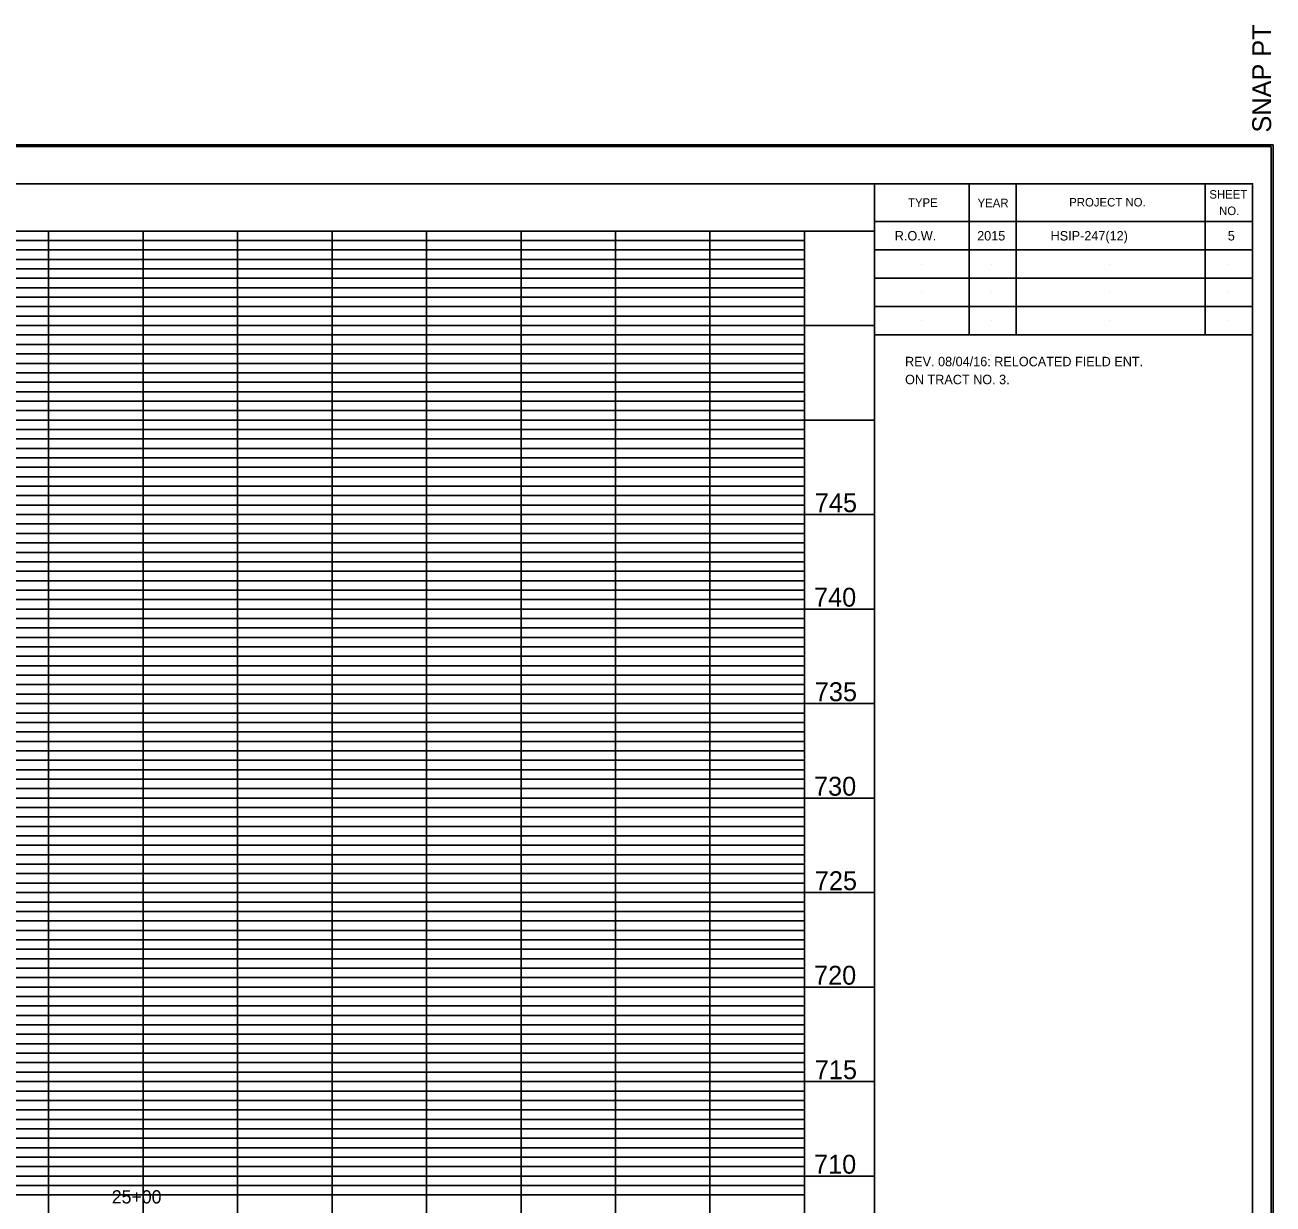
# Model space of a CAD drawing. Extents: x -200 to 1681865, y -325 to 520634.
# Drawn here: x 1681205 to 1681865, y 520010 to 520634 of the extents above; entities that cross this region are included whole.
import ezdxf

# ---------------------------------------------------------------- set-up
doc = ezdxf.new("R2010")
doc.units = 0
for name, color, linetype in [('DESIGN - SCRATCH - User 1', 7, 'Continuous'), ('DESIGN - SHEET - Corner Text', 7, 'Continuous'), ('DESIGN - SHEET - Light Grid', 7, 'Continuous'), ('DESIGN - SHEET - Linework', 7, 'Continuous'), ('DESIGN - SHEET - Plot Shape', 7, 'Continuous')]:
    doc.layers.add(name, color=color, linetype=linetype)

msp = doc.modelspace()

# ---------------------------------------------------------------- linework, layer by layer
at = {"layer": 'DESIGN - SCRATCH - User 1'}
for p, q in [((1681679.23, 520522.26), (1681679.23, 520522.26)), ((1681716.23, 520522.26), (1681716.23, 520522.26)), ((1681778.73, 520522.26), (1681778.73, 520522.26)), ((1681841.23, 520522.26), (1681841.23, 520522.26)), ((1681679.23, 520507.26), (1681679.23, 520507.26)), ((1681716.23, 520507.26), (1681716.23, 520507.26)), ((1681778.73, 520507.26), (1681778.73, 520507.26)), ((1681841.23, 520507.26), (1681841.23, 520507.26)), ((1681679.23, 520492.26), (1681679.23, 520492.26)), ((1681716.23, 520492.26), (1681716.23, 520492.26)), ((1681778.73, 520492.26), (1681778.73, 520492.26)), ((1681841.23, 520492.26), (1681841.23, 520492.26)), ((1681679.23, 520477.26), (1681679.23, 520477.26)), ((1681716.23, 520477.26), (1681716.23, 520477.26)), ((1681778.73, 520477.26), (1681778.73, 520477.26)), ((1681841.23, 520477.26), (1681841.23, 520477.26))]:
    msp.add_line(p, q, dxfattribs=at)
at = {"layer": 'DESIGN - SHEET - Light Grid'}
for p, q in [((1680967.13, 520519.76), (1681317.13, 520519.76)), ((1680967.13, 520514.76), (1681317.13, 520514.76)), ((1681317.13, 520519.76), (1681617.13, 520519.76)), ((1681317.13, 520514.76), (1681617.13, 520514.76)), ((1680967.13, 520509.76), (1681317.13, 520509.76)), ((1681317.13, 520509.76), (1681617.13, 520509.76)), ((1680967.13, 520504.76), (1681317.13, 520504.76)), ((1681317.13, 520504.76), (1681617.13, 520504.76)), ((1680967.13, 520499.76), (1681317.13, 520499.76)), ((1680967.13, 520494.76), (1681317.13, 520494.76)), ((1681317.13, 520499.76), (1681617.13, 520499.76)), ((1681317.13, 520494.76), (1681617.13, 520494.76)), ((1680967.13, 520489.76), (1681317.13, 520489.76)), ((1681317.13, 520489.76), (1681617.13, 520489.76)), ((1680967.13, 520484.76), (1681317.13, 520484.76)), ((1681317.13, 520484.76), (1681617.13, 520484.76)), ((1680967.13, 520479.76), (1681317.13, 520479.76)), ((1681317.13, 520479.76), (1681617.13, 520479.76)), ((1680967.13, 520469.76), (1681317.13, 520469.76)), ((1681317.13, 520469.76), (1681617.13, 520469.76)), ((1680967.13, 520464.76), (1681317.13, 520464.76)), ((1681317.13, 520464.76), (1681617.13, 520464.76)), ((1680967.13, 520459.76), (1681317.13, 520459.76)), ((1680967.13, 520454.76), (1681317.13, 520454.76)), ((1681317.13, 520459.76), (1681617.13, 520459.76)), ((1681317.13, 520454.76), (1681617.13, 520454.76)), ((1680967.13, 520449.76), (1681317.13, 520449.76)), ((1681317.13, 520449.76), (1681617.13, 520449.76)), ((1680967.13, 520444.76), (1681317.13, 520444.76)), ((1681317.13, 520444.76), (1681617.13, 520444.76)), ((1680967.13, 520439.76), (1681317.13, 520439.76)), ((1680967.13, 520434.76), (1681317.13, 520434.76)), ((1681317.13, 520439.76), (1681617.13, 520439.76)), ((1681317.13, 520434.76), (1681617.13, 520434.76)), ((1680967.13, 520429.76), (1681317.13, 520429.76)), ((1681317.13, 520429.76), (1681617.13, 520429.76)), ((1680967.13, 520419.76), (1681317.13, 520419.76)), ((1681317.13, 520419.76), (1681617.13, 520419.76)), ((1680967.13, 520414.76), (1681317.13, 520414.76)), ((1680967.13, 520409.76), (1681317.13, 520409.76)), ((1681317.13, 520414.76), (1681617.13, 520414.76)), ((1681317.13, 520409.76), (1681617.13, 520409.76)), ((1680967.13, 520404.76), (1681317.13, 520404.76)), ((1681317.13, 520404.76), (1681617.13, 520404.76)), ((1680967.13, 520399.76), (1681317.13, 520399.76)), ((1681317.13, 520399.76), (1681617.13, 520399.76)), ((1680967.13, 520394.76), (1681317.13, 520394.76)), ((1680967.13, 520389.76), (1681317.13, 520389.76)), ((1681317.13, 520394.76), (1681617.13, 520394.76)), ((1681317.13, 520389.76), (1681617.13, 520389.76)), ((1680967.13, 520384.76), (1681317.13, 520384.76)), ((1681317.13, 520384.76), (1681617.13, 520384.76)), ((1680967.13, 520379.76), (1681317.13, 520379.76)), ((1681317.13, 520379.76), (1681617.13, 520379.76)), ((1680967.13, 520369.76), (1681317.13, 520369.76)), ((1681317.13, 520369.76), (1681617.13, 520369.76)), ((1680967.13, 520364.76), (1681317.13, 520364.76)), ((1681317.13, 520364.76), (1681617.13, 520364.76)), ((1680967.13, 520359.76), (1681317.13, 520359.76)), ((1681317.13, 520359.76), (1681617.13, 520359.76)), ((1680967.13, 520354.76), (1681317.13, 520354.76)), ((1680967.13, 520349.76), (1681317.13, 520349.76)), ((1681317.13, 520354.76), (1681617.13, 520354.76)), ((1681317.13, 520349.76), (1681617.13, 520349.76)), ((1680967.13, 520344.76), (1681317.13, 520344.76)), ((1681317.13, 520344.76), (1681617.13, 520344.76)), ((1680967.13, 520339.76), (1681317.13, 520339.76)), ((1681317.13, 520339.76), (1681617.13, 520339.76)), ((1680967.13, 520334.76), (1681317.13, 520334.76)), ((1680967.13, 520329.76), (1681317.13, 520329.76)), ((1681317.13, 520334.76), (1681617.13, 520334.76)), ((1681317.13, 520329.76), (1681617.13, 520329.76)), ((1680967.13, 520319.76), (1681317.13, 520319.76)), ((1681317.13, 520319.76), (1681617.13, 520319.76)), ((1680967.13, 520314.76), (1681317.13, 520314.76)), ((1680967.13, 520309.76), (1681317.13, 520309.76)), ((1681317.13, 520314.76), (1681617.13, 520314.76)), ((1681317.13, 520309.76), (1681617.13, 520309.76)), ((1680967.13, 520304.76), (1681317.13, 520304.76)), ((1681317.13, 520304.76), (1681617.13, 520304.76)), ((1680967.13, 520299.76), (1681317.13, 520299.76)), ((1681317.13, 520299.76), (1681617.13, 520299.76)), ((1680967.13, 520294.76), (1681317.13, 520294.76)), ((1680967.13, 520289.76), (1681317.13, 520289.76)), ((1681317.13, 520294.76), (1681617.13, 520294.76)), ((1681317.13, 520289.76), (1681617.13, 520289.76)), ((1680967.13, 520284.76), (1681317.13, 520284.76)), ((1681317.13, 520284.76), (1681617.13, 520284.76)), ((1680967.13, 520279.76), (1681317.13, 520279.76)), ((1681317.13, 520279.76), (1681617.13, 520279.76)), ((1680967.13, 520269.76), (1681317.13, 520269.76)), ((1681317.13, 520269.76), (1681617.13, 520269.76)), ((1680967.13, 520264.76), (1681317.13, 520264.76)), ((1681317.13, 520264.76), (1681617.13, 520264.76)), ((1680967.13, 520259.76), (1681317.13, 520259.76)), ((1681317.13, 520259.76), (1681617.13, 520259.76)), ((1680967.13, 520254.76), (1681317.13, 520254.76)), ((1680967.13, 520249.76), (1681317.13, 520249.76)), ((1681317.13, 520254.76), (1681617.13, 520254.76)), ((1681317.13, 520249.76), (1681617.13, 520249.76)), ((1680967.13, 520244.76), (1681317.13, 520244.76)), ((1681317.13, 520244.76), (1681617.13, 520244.76)), ((1680967.13, 520239.76), (1681317.13, 520239.76)), ((1681317.13, 520239.76), (1681617.13, 520239.76)), ((1680967.13, 520234.76), (1681317.13, 520234.76)), ((1681317.13, 520234.76), (1681617.13, 520234.76)), ((1680967.13, 520229.76), (1681317.13, 520229.76)), ((1681317.13, 520229.76), (1681617.13, 520229.76)), ((1680967.13, 520219.76), (1681317.13, 520219.76)), ((1681317.13, 520219.76), (1681617.13, 520219.76)), ((1680967.13, 520214.76), (1681317.13, 520214.76)), ((1681317.13, 520214.76), (1681617.13, 520214.76)), ((1680967.13, 520209.76), (1681317.13, 520209.76)), ((1680967.13, 520204.76), (1681317.13, 520204.76)), ((1681317.13, 520209.76), (1681617.13, 520209.76)), ((1681317.13, 520204.76), (1681617.13, 520204.76)), ((1680967.13, 520199.76), (1681317.13, 520199.76)), ((1681317.13, 520199.76), (1681617.13, 520199.76)), ((1680967.13, 520194.76), (1681317.13, 520194.76)), ((1681317.13, 520194.76), (1681617.13, 520194.76)), ((1680967.13, 520189.76), (1681317.13, 520189.76)), ((1680967.13, 520184.76), (1681317.13, 520184.76)), ((1681317.13, 520189.76), (1681617.13, 520189.76)), ((1681317.13, 520184.76), (1681617.13, 520184.76)), ((1680967.13, 520179.76), (1681317.13, 520179.76)), ((1681317.13, 520179.76), (1681617.13, 520179.76)), ((1680967.13, 520169.76), (1681317.13, 520169.76)), ((1680967.13, 520164.76), (1681317.13, 520164.76)), ((1681317.13, 520169.76), (1681617.13, 520169.76)), ((1681317.13, 520164.76), (1681617.13, 520164.76)), ((1680967.13, 520159.76), (1681317.13, 520159.76)), ((1681317.13, 520159.76), (1681617.13, 520159.76)), ((1680967.13, 520154.76), (1681317.13, 520154.76)), ((1681317.13, 520154.76), (1681617.13, 520154.76)), ((1680967.13, 520149.76), (1681317.13, 520149.76)), ((1680967.13, 520144.76), (1681317.13, 520144.76)), ((1681317.13, 520149.76), (1681617.13, 520149.76)), ((1681317.13, 520144.76), (1681617.13, 520144.76)), ((1680967.13, 520139.76), (1681317.13, 520139.76)), ((1681317.13, 520139.76), (1681617.13, 520139.76)), ((1680967.13, 520134.76), (1681317.13, 520134.76)), ((1681317.13, 520134.76), (1681617.13, 520134.76)), ((1680967.13, 520129.76), (1681317.13, 520129.76)), ((1681317.13, 520129.76), (1681617.13, 520129.76)), ((1680967.13, 520119.76), (1681317.13, 520119.76)), ((1681317.13, 520119.76), (1681617.13, 520119.76)), ((1680967.13, 520114.76), (1681317.13, 520114.76)), ((1681317.13, 520114.76), (1681617.13, 520114.76)), ((1680967.13, 520109.76), (1681317.13, 520109.76)), ((1680967.13, 520104.76), (1681317.13, 520104.76)), ((1681317.13, 520109.76), (1681617.13, 520109.76)), ((1681317.13, 520104.76), (1681617.13, 520104.76)), ((1680967.13, 520099.76), (1681317.13, 520099.76)), ((1681317.13, 520099.76), (1681617.13, 520099.76)), ((1680967.13, 520094.76), (1681317.13, 520094.76)), ((1681317.13, 520094.76), (1681617.13, 520094.76)), ((1680967.13, 520089.76), (1681317.13, 520089.76)), ((1680967.13, 520084.76), (1681317.13, 520084.76)), ((1681317.13, 520089.76), (1681617.13, 520089.76)), ((1681317.13, 520084.76), (1681617.13, 520084.76)), ((1680967.13, 520079.76), (1681317.13, 520079.76)), ((1681317.13, 520079.76), (1681617.13, 520079.76)), ((1680967.13, 520069.76), (1681317.13, 520069.76)), ((1680967.13, 520064.76), (1681317.13, 520064.76)), ((1681317.13, 520069.76), (1681617.13, 520069.76)), ((1681317.13, 520064.76), (1681617.13, 520064.76)), ((1680967.13, 520059.76), (1681317.13, 520059.76)), ((1681317.13, 520059.76), (1681617.13, 520059.76)), ((1680967.13, 520054.76), (1681317.13, 520054.76)), ((1681317.13, 520054.76), (1681617.13, 520054.76)), ((1680967.13, 520049.76), (1681317.13, 520049.76)), ((1681317.13, 520049.76), (1681617.13, 520049.76)), ((1680967.13, 520044.76), (1681317.13, 520044.76)), ((1680967.13, 520039.76), (1681317.13, 520039.76)), ((1681317.13, 520044.76), (1681617.13, 520044.76)), ((1681317.13, 520039.76), (1681617.13, 520039.76)), ((1680967.13, 520034.76), (1681317.13, 520034.76)), ((1681317.13, 520034.76), (1681617.13, 520034.76)), ((1680967.13, 520029.76), (1681317.13, 520029.76)), ((1681317.13, 520029.76), (1681617.13, 520029.76)), ((1680967.13, 520019.76), (1681317.13, 520019.76)), ((1681317.13, 520019.76), (1681617.13, 520019.76)), ((1680967.13, 520014.76), (1681317.13, 520014.76)), ((1681317.13, 520014.76), (1681617.13, 520014.76))]:
    msp.add_line(p, q, dxfattribs=at)
at = {"layer": 'DESIGN - SHEET - Linework'}
for p, q in [((1680163.08, 520570.46), (1681865.08, 520570.46)), ((1681865.08, 520570.46), (1681865.08, 519479.06)), ((1680282.13, 520524.76), (1681654.23, 520524.76)), ((1681217.13, 519524.76), (1681217.13, 520524.76)), ((1681267.13, 519524.76), (1681267.13, 520524.76)), ((1681317.13, 519524.76), (1681317.13, 520524.76)), ((1681367.13, 519524.76), (1681367.13, 520524.76)), ((1681417.13, 519524.76), (1681417.13, 520524.76)), ((1681467.13, 519524.76), (1681467.13, 520524.76)), ((1681517.13, 519524.76), (1681517.13, 520524.76)), ((1681567.13, 519524.76), (1681567.13, 520524.76)), ((1681617.13, 519524.76), (1681617.13, 520524.76)), ((1680280.03, 520474.76), (1681654.23, 520474.76)), ((1680280.03, 520424.76), (1681654.23, 520424.76)), ((1680280.03, 520374.76), (1681654.23, 520374.76)), ((1680280.03, 520324.76), (1681654.23, 520324.76)), ((1680280.03, 520274.76), (1681654.23, 520274.76)), ((1680280.03, 520224.76), (1681654.23, 520224.76)), ((1680280.03, 520174.76), (1681654.23, 520174.76)), ((1680280.03, 520124.76), (1681654.23, 520124.76)), ((1680280.03, 520074.76), (1681654.23, 520074.76)), ((1680280.03, 520024.76), (1681654.23, 520024.76))]:
    msp.add_line(p, q, dxfattribs=at)
for points in [[(1680280.03, 520549.76), (1680280.03, 519499.76), (1681854.23, 519499.76), (1681854.23, 520549.76), (1680280.03, 520549.76)], [(1681654.23, 520549.76), (1681654.23, 520469.76), (1681854.23, 520469.76), (1681854.23, 520549.76), (1681829.23, 520549.76), (1681829.23, 520469.76), (1681729.23, 520469.76), (1681729.23, 520549.76), (1681704.23, 520549.76), (1681704.23, 520469.76), (1681654.23, 520469.76), (1681654.23, 520484.76), (1681854.23, 520484.76), (1681854.23, 520499.76), (1681654.23, 520499.76), (1681654.23, 520514.76), (1681854.23, 520514.76), (1681854.23, 520529.76), (1681654.23, 520529.76)], [(1680280.03, 519524.76), (1680280.03, 520524.76), (1681654.23, 520524.76), (1681654.23, 519524.76), (1680282.13, 519524.76)]]:
    msp.add_lwpolyline(points, dxfattribs=at)
at = {"layer": 'DESIGN - SHEET - Plot Shape'}
for points in [[(1680164.08, 520569.46), (1681864.08, 520569.46), (1681864.08, 519480.06), (1680164.08, 519480.06)], [(1680194.98, 520549.76), (1681854.23, 520549.76), (1681854.23, 519499.76), (1680194.98, 519499.76)]]:
    msp.add_lwpolyline(points, close=True, dxfattribs=at)

# ---------------------------------------------------------------- texts
at = {"layer": 'DESIGN - SHEET - Corner Text'}
for s, height, rotation, p in [('  SNAP PT', 10, 90, (1681864.08, 520569.46)), ('REV. 08/04/16: RELOCATED FIELD ENT.', 5, 360, (1681670.36, 520453.22)), ('ON TRACT NO. 3.', 5, 360, (1681670.36, 520443.72))]:
    msp.add_text(s, height=height, rotation=rotation, dxfattribs=at).set_placement(p)
for s, height, p in [('TYPE', 4.5, (1681671.93, 520537.56)), ('YEAR', 4.5, (1681708.73, 520537.36)), ('PROJECT NO.', 4.5, (1681757.23, 520537.76)), ('SHEET', 4.5, (1681831.38, 520541.91)), ('NO.', 4.5, (1681836.53, 520533.21)), ('  R.O.W.  ', 5, (1681661.21, 520519.76)), ('2015', 5, (1681708.51, 520519.76)), ('    HSIP-247(12)    ', 5, (1681739.95, 520519.76)), ('5', 5, (1681841.16, 520519.76)), ('745', 10, (1681622.62, 520376.02)), ('740', 10, (1681622.19, 520326.02)), ('735', 10, (1681622.62, 520276.02)), ('730', 10, (1681622.19, 520226.02)), ('725', 10, (1681622.62, 520176.02)), ('720', 10, (1681622.19, 520126.02)), ('715', 10, (1681622.62, 520076.02)), ('710', 10, (1681622.19, 520026.02)), ('25+00', 7, (1681250.58, 520010.26))]:
    msp.add_text(s, height=height, dxfattribs=at).set_placement(p)

doc.saveas('drawing.dxf')
